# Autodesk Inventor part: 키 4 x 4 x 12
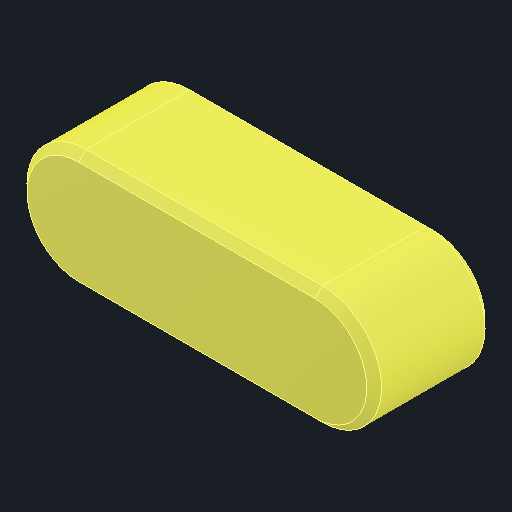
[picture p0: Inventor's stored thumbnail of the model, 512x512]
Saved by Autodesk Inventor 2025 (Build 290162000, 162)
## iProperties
Created: 2025-08
Part Number: 키 4 x 4 x 12
Material: 강철, 연강
Description: 키 및 해당 키홈
Document SubType Name: Modeling
Designer: infra002
Density: 7.85 g/cm^3
Appearance: 기본값
Author: jhkim
Sending System: Autodesk Inventor 2026
Preprocessor: ST-DEVELOPER v20.1
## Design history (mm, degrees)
feature "Solid1"
node "솔리드1"
